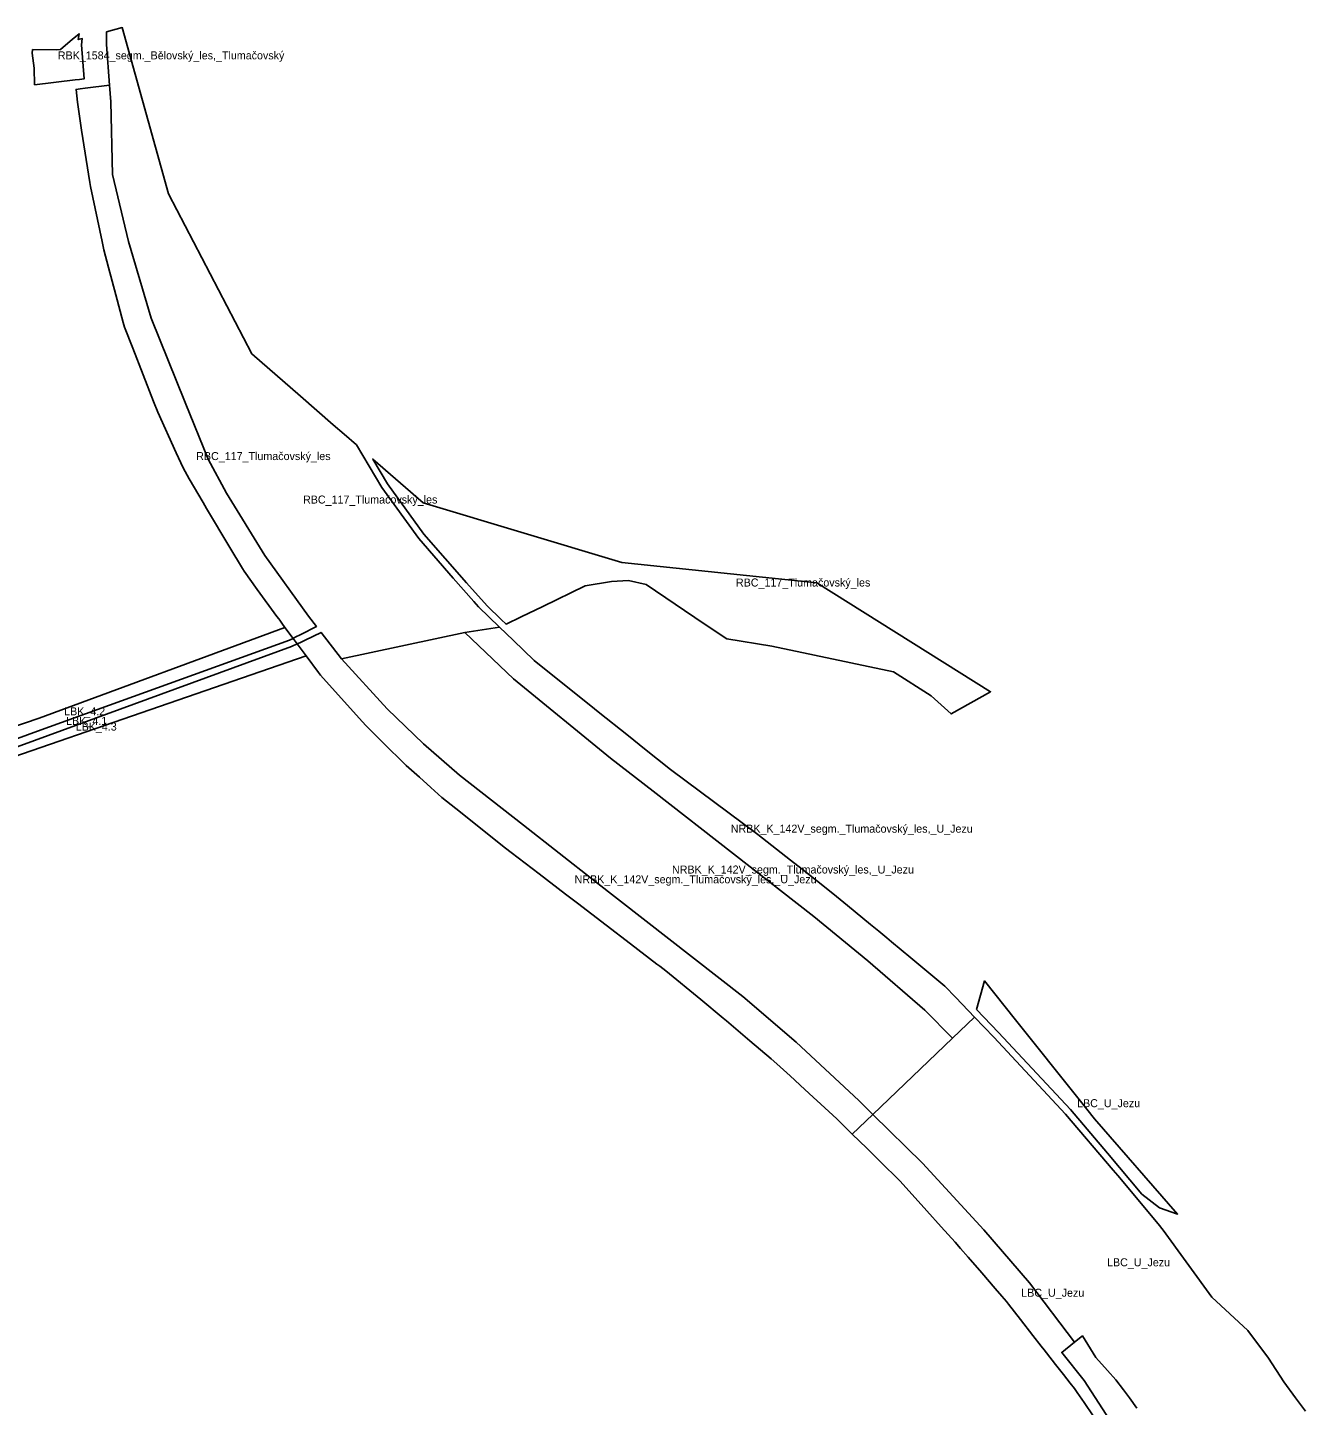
# Model space of a CAD drawing. Extents: x -535894 to -532763, y -1165802 to -1163647.
# Drawn here: x -533885 to -533086, y -1164727 to -1163866 of the extents above; entities that cross this region are included whole.
import ezdxf

# ---------------------------------------------------------------- set-up
doc = ezdxf.new("R2010")
doc.units = 0
for name, color, linetype in [('91230013', 7, 'Continuous'), ('91230023', 7, 'Continuous'), ('91250013', 7, 'Continuous'), ('91250023', 7, 'Continuous'), ('91260023', 7, 'Continuous'), ('91270013', 7, 'Continuous'), ('91270023', 7, 'Continuous'), ('91280013', 7, 'Continuous'), ('91280023', 7, 'Continuous')]:
    doc.layers.add(name, color=color, linetype=linetype)

msp = doc.modelspace()

# ---------------------------------------------------------------- linework, layer by layer
at = {"layer": '91230013'}
msp.add_lwpolyline([(-533356.161, -1164545.372), (-533365.03, -1164536.67), (-533404.17, -1164500.26), (-533437.52, -1164471.63), (-533529.97, -1164399.56), (-533574.57, -1164364.55), (-533614.65, -1164333.34), (-533637.12, -1164313.74), (-533659.7, -1164292.03), (-533688.28, -1164260.76), (-533611.129, -1164244.351), (-533580.88, -1164273.2), (-533520.08, -1164322.87), (-533493.52, -1164343.51), (-533393.01, -1164421.73), (-533359.31, -1164449.39), (-533323.6, -1164480.19), (-533306.34, -1164497.645)], close=True, dxfattribs=at)
at = {"layer": '91230023'}
for points in [[(-533365.03, -1164536.67), (-533356.161, -1164545.372), (-533369.01, -1164557.68), (-533376.87, -1164549.96), (-533378.75, -1164548.22), (-533388.71, -1164539.01), (-533393.52, -1164534.57), (-533398.68, -1164529.8), (-533407.83, -1164521.35), (-533416.13, -1164513.68), (-533419.75, -1164510.6), (-533433.01, -1164499.36), (-533447.72, -1164486.86), (-533449.65, -1164485.24), (-533463.74, -1164473.66), (-533485.66, -1164455.66), (-533489.36, -1164452.83), (-533491.1, -1164451.5), (-533507.65, -1164438.78), (-533522.97, -1164427.03), (-533540.77, -1164413.38), (-533548.26, -1164407.66), (-533564.8, -1164395.06), (-533582.28, -1164381.75), (-533585.87, -1164379.01), (-533616.81, -1164354.28), (-533625.55, -1164347.3), (-533632.43, -1164341.14), (-533639.6, -1164334.73), (-533647.79, -1164327.4), (-533662.64, -1164312.76), (-533673.2, -1164302.34), (-533677.32, -1164297.76), (-533701.48, -1164270.84), (-533702.69, -1164269.23), (-533710.415, -1164258.881), (-533716.005, -1164251.393), (-533714.4, -1164250.627), (-533710.987, -1164248.998), (-533701.07, -1164244.265), (-533688.28, -1164260.76), (-533659.7, -1164292.03), (-533637.12, -1164313.74), (-533614.65, -1164333.34), (-533574.57, -1164364.55), (-533529.97, -1164399.56), (-533437.52, -1164471.63), (-533404.17, -1164500.26)], [(-533611.129, -1164244.351), (-533589.48, -1164241.027), (-533581.099, -1164249.121), (-533567.95, -1164261.82), (-533530.25, -1164291.87), (-533527.78, -1164293.84), (-533508.97, -1164308.83), (-533498.95, -1164316.9), (-533482.76, -1164329.92), (-533428.16, -1164370.44), (-533407.7, -1164386.45), (-533400.38, -1164392.18), (-533391.36, -1164399.24), (-533381.09, -1164407.28), (-533371.94, -1164414.84), (-533357.65, -1164426.65), (-533352.45, -1164430.94), (-533347.48, -1164435.05), (-533344.43, -1164437.59), (-533332.48, -1164447.55), (-533320, -1164457.95), (-533311.26, -1164465.24), (-533304.36, -1164472.39), (-533292.65, -1164484.53), (-533306.34, -1164497.645), (-533323.6, -1164480.19), (-533359.31, -1164449.39), (-533393.01, -1164421.73), (-533493.52, -1164343.51), (-533520.08, -1164322.87), (-533580.88, -1164273.2)]]:
    msp.add_lwpolyline(points, close=True, dxfattribs=at)
at = {"layer": '91250013'}
for points in [[(-533678.92, -1164127.1), (-533663.1, -1164153.72), (-533640.06, -1164185.46), (-533618.43, -1164210.24), (-533605.59, -1164224.96), (-533602.74, -1164228.22), (-533589.48, -1164241.027), (-533611.129, -1164244.351), (-533688.28, -1164260.76), (-533701.07, -1164244.265), (-533710.987, -1164248.998), (-533714.4, -1164250.627), (-533716.005, -1164251.393), (-533718.598, -1164247.919), (-533717.204, -1164247.203), (-533713.812, -1164245.458), (-533704.042, -1164240.432), (-533708.99, -1164234.05), (-533736.29, -1164196.18), (-533760.11, -1164157.23), (-533771.58, -1164135.97), (-533785.98, -1164100.6), (-533807.37, -1164047.78), (-533821.43, -1163999.88), (-533831.47, -1163958.19), (-533832.51, -1163912.75), (-533833.31, -1163902.268), (-533835.25, -1163876.86), (-533835.15, -1163868.99), (-533825.35, -1163866.3), (-533796.36, -1163970.1), (-533744.41, -1164070.17), (-533714.01, -1164096.6), (-533693.46, -1164114.46), (-533686.62, -1164120.4)], [(-533637.25, -1164163.31), (-533513.14, -1164200.59), (-533391.15, -1164213.21), (-533282.63, -1164281.27), (-533307.29, -1164295.19), (-533319.79, -1164283.92), (-533343.32, -1164268.94), (-533419.39, -1164252.85), (-533447.47, -1164248.27), (-533461.562, -1164238.775), (-533497.797, -1164214.361), (-533508.828, -1164211.815), (-533519.496, -1164212.422), (-533536.104, -1164215.21), (-533562.456, -1164227.956), (-533575.957, -1164234.486), (-533585.451, -1164239.078), (-533588.575, -1164236.061), (-533597.315, -1164227.62), (-533610.265, -1164213.212), (-533636.772, -1164182.84), (-533659.588, -1164151.409), (-533668.817, -1164135.879)]]:
    msp.add_lwpolyline(points, close=True, dxfattribs=at)
at = {"layer": '91250023'}
msp.add_lwpolyline([(-533740.96, -1164217.33), (-533749.2, -1164206.03), (-533750.29, -1164204.21), (-533758.05, -1164191.21), (-533772.63, -1164166.78), (-533774.86, -1164162.96), (-533783.44, -1164148.24), (-533787.38, -1164141.47), (-533791.66, -1164132.02), (-533803.18, -1164106.57), (-533805.75, -1164099.98), (-533818.83, -1164066.55), (-533823.91, -1164053.54), (-533824.72, -1164050.56), (-533829.37, -1164033.3), (-533833.99, -1164016.17), (-533836.92, -1164005.27), (-533838.01, -1164000.05), (-533845.21, -1163965.55), (-533845.71, -1163963.15), (-533850.77, -1163930.31), (-533853.43, -1163913.02), (-533854.207, -1163904.974), (-533851.572, -1163904.633), (-533848.562, -1163904.243), (-533833.31, -1163902.268), (-533832.51, -1163912.75), (-533831.47, -1163958.19), (-533821.43, -1163999.88), (-533807.37, -1164047.78), (-533785.98, -1164100.6), (-533771.58, -1164135.97), (-533760.11, -1164157.23), (-533736.29, -1164196.18), (-533708.99, -1164234.05), (-533704.042, -1164240.432), (-533713.812, -1164245.458), (-533717.204, -1164247.203), (-533718.598, -1164247.919), (-533723.64, -1164241.09), (-533725.58, -1164238.43), (-533726.88, -1164236.66), (-533727.58, -1164235.7), (-533728.64, -1164234.23)], close=True, dxfattribs=at)
at = {"layer": '91260023'}
msp.add_lwpolyline([(-533880.128, -1163902.177), (-533880.47, -1163891.74), (-533881.62, -1163882.25), (-533881.4, -1163880.05), (-533866.68, -1163880.24), (-533863.98, -1163879.91), (-533856.45, -1163873.6), (-533853.53, -1163871.16), (-533852.38, -1163870.19), (-533852.91, -1163873.85), (-533850.38, -1163873.16), (-533850.88, -1163877.07), (-533849.072, -1163898.259), (-533852.16, -1163898.659), (-533854.784, -1163898.999)], close=True, dxfattribs=at)
at = {"layer": '91270013'}
msp.add_lwpolyline([(-533217.69, -1164548.05), (-533165.64, -1164607.65), (-533177.04, -1164603.82), (-533187.972, -1164595.15), (-533209.403, -1164569.613), (-533232.543, -1164542.376), (-533277.572, -1164494.141), (-533291.333, -1164479.846), (-533286.31, -1164461.99), (-533266.97, -1164486.26), (-533227.22, -1164536.15)], close=True, dxfattribs=at)
msp.add_lwpolyline([(-533191.148, -1164728.822), (-533195.682, -1164722.466), (-533199.44, -1164717.478), (-533204.377, -1164711.27), (-533209.409, -1164705.307), (-533216.777, -1164697.165), (-533225.204, -1164683.758), (-533230.072, -1164687.654), (-533258.18, -1164650.51), (-533286.88, -1164617.4), (-533325.21, -1164575.74), (-533356.161, -1164545.372), (-533306.34, -1164497.645), (-533292.65, -1164484.53), (-533280.62, -1164497.03), (-533235.68, -1164545.17), (-533205.86, -1164580.27), (-533203.109, -1164583.566), (-533177.92, -1164613.75), (-533174.61, -1164617.7), (-533144.204, -1164659.543), (-533121.714, -1164680.309), (-533108.898, -1164697.684), (-533099.18, -1164712.521), (-533091.952, -1164722.472), (-533090.161, -1164724.938), (-533085.762, -1164730.682)], dxfattribs=at)
at = {"layer": '91270023'}
msp.add_lwpolyline([(-533218.37, -1164733.63), (-533224.16, -1164725.28), (-533228.43, -1164719.12), (-533230.18, -1164716.6), (-533232.82, -1164713.23), (-533237.07, -1164707.79), (-533241.91, -1164701.61), (-533244.066, -1164698.853), (-533249.02, -1164692.52), (-533250.95, -1164690.07), (-533256.12, -1164683.46), (-533263.96, -1164673.42), (-533271.44, -1164663.87), (-533272.67, -1164662.3), (-533275.61, -1164658.9), (-533279.79, -1164654.05), (-533288.14, -1164644.37), (-533296.52, -1164634.66), (-533301.29, -1164629.13), (-533304.78, -1164625.25), (-533313.54, -1164615.51), (-533322.44, -1164605.61), (-533339.13, -1164587.05), (-533340.54, -1164585.66), (-533350.43, -1164575.94), (-533359.97, -1164566.56), (-533369.01, -1164557.68), (-533356.161, -1164545.372), (-533325.21, -1164575.74), (-533286.88, -1164617.4), (-533258.18, -1164650.51), (-533230.072, -1164687.654), (-533238.085, -1164694.066), (-533224.07, -1164711.63), (-533183.34, -1164774.65)], dxfattribs=at)
at = {"layer": '91280013'}
msp.add_lwpolyline([(-534008.513, -1164350.985), (-533994.159, -1164345.79), (-533913.758, -1164318.806), (-533878.291, -1164305.987), (-533720.886, -1164249.096), (-533718.598, -1164247.919), (-533716.005, -1164251.393), (-533719.497, -1164253.06), (-533908.348, -1164321.995), (-533992.489, -1164350.51), (-534008.777, -1164356.096), (-534008.751, -1164353.346)], close=True, dxfattribs=at)
at = {"layer": '91280023'}
for points in [[(-533720.886, -1164249.096), (-533878.291, -1164305.987), (-533913.758, -1164318.806), (-533994.159, -1164345.79), (-534008.513, -1164350.985), (-534007.911, -1164344.987), (-534005.963, -1164337.46), (-534000.781, -1164338.991), (-533998.54, -1164338.94), (-533877.27, -1164297.75), (-533723.64, -1164241.09), (-533718.598, -1164247.919)], [(-533716.005, -1164251.393), (-533710.415, -1164258.881), (-534002.49, -1164359.73), (-534008.797, -1164358.709), (-534008.777, -1164356.096), (-533992.489, -1164350.51), (-533908.348, -1164321.995), (-533719.497, -1164253.06)]]:
    msp.add_lwpolyline(points, close=True, dxfattribs=at)

# ---------------------------------------------------------------- texts
at = {"layer": '91230013'}
msp.add_text('NRBK_K_142V_segm._Tlumačovský_les,_U_Jezu', height=5, rotation=0, dxfattribs=at).set_placement((-533481.7453, -1164394.8615))
at = {"layer": '91230023'}
for rotation, p in [(360, (-533444.9911, -1164369.336)), (0.0000001, (-533542.5984, -1164400.9725))]:
    msp.add_text('NRBK_K_142V_segm._Tlumačovský_les,_U_Jezu', height=5, rotation=rotation, dxfattribs=at).set_placement(p)
at = {"layer": '91250013'}
for rotation, p in [(0, (-533712.365, -1164163.699)), (360, (-533441.7495, -1164215.5345))]:
    msp.add_text('RBC_117_Tlumačovský_les', height=5, rotation=rotation, dxfattribs=at).set_placement(p)
at = {"layer": '91250023'}
msp.add_text('RBC_117_Tlumačovský_les', height=5, rotation=0, dxfattribs=at).set_placement((-533779.1245, -1164136.5413))
at = {"layer": '91260023'}
msp.add_text('RBK_1584_segm._Bělovský_les,_Tlumačovský', height=5, rotation=359.9999999, dxfattribs=at).set_placement((-533865.6229, -1163886.1835))
at = {"layer": '91270013'}
for rotation, p in [(0, (-533228.4865, -1164540.8556)), (360, (-533209.7855, -1164640.2702))]:
    msp.add_text('LBC_U_Jezu', height=5, rotation=rotation, dxfattribs=at).set_placement(p)
at = {"layer": '91270023'}
msp.add_text('LBC_U_Jezu', height=5, rotation=360, dxfattribs=at).set_placement((-533263.42, -1164659.2882))
at = {"layer": '91280013'}
msp.add_text('LBK_4.1', height=5, rotation=360, dxfattribs=at).set_placement((-533860.4359, -1164302.0075))
at = {"layer": '91280023'}
for s, rotation, p in [('LBK_4.2', 0, (-533861.6948, -1164296.0375)), ('LBK_4.3', 359.9999999, (-533854.4684, -1164305.5615))]:
    msp.add_text(s, height=5, rotation=rotation, dxfattribs=at).set_placement(p)

doc.saveas('drawing.dxf')
